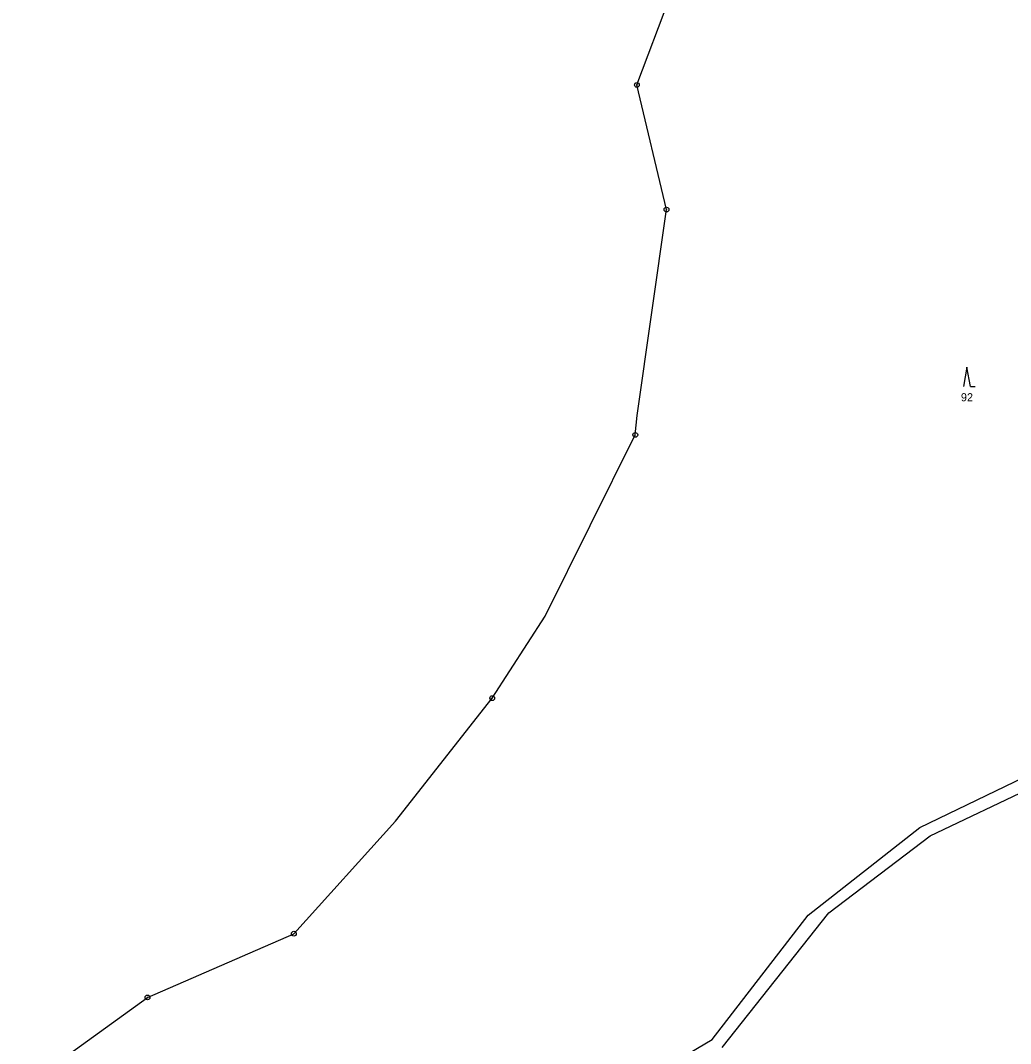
# Model space of a CAD drawing. Extents: x -601877 to -599786, y -1122905 to -1121218.
# Drawn here: x -601358.8 to -601151.3, y -1121749.5 to -1121535.2 of the extents above; entities that cross this region are included whole.
import ezdxf
from ezdxf.enums import TextEntityAlignment as Align

# ---------------------------------------------------------------- set-up
doc = ezdxf.new("R2010")
doc.units = 0
doc.header["$LTSCALE"] = 0.68
for name, color, linetype, lineweight in [('1', 7, 'Continuous', 25), ('3', 7, 'Continuous', 25), ('8', 7, 'Continuous', 25)]:
    doc.layers.add(name, color=color, linetype=linetype, lineweight=lineweight)
doc.layers.add('2', color=7, linetype='Continuous')

msp = doc.modelspace()

# ---------------------------------------------------------------- linework, layer by layer
at = {"layer": '1'}
for p, q in [((-601229.61, -1121548.67), (-601218.56, -1121519.2)), ((-601223.41, -1121574.79), (-601229.61, -1121548.67)), ((-601229.57, -1121617.92), (-601223.41, -1121574.79)), ((-601229.95, -1121622), (-601229.57, -1121617.92)), ((-601248.82, -1121660.01), (-601229.95, -1121622)), ((-601259.92, -1121677.17), (-601248.82, -1121660.01)), ((-601280.22, -1121702.97), (-601259.92, -1121677.17)), ((-601170.32, -1121704.29), (-601111.3, -1121675.76)), ((-601168.15, -1121706.02), (-601108.49, -1121677.47)), ((-601301.49, -1121726.53), (-601280.22, -1121702.97)), ((-601193.74, -1121722.61), (-601170.32, -1121704.29)), ((-601189.37, -1121722.16), (-601168.15, -1121706.02)), ((-601211.78, -1121750.4), (-601189.37, -1121722.16)), ((-601213.82, -1121748.69), (-601193.74, -1121722.61)), ((-601332.16, -1121739.88), (-601301.49, -1121726.53)), ((-601358.77, -1121759.06), (-601332.16, -1121739.88)), ((-601220.34, -1121752.57), (-601213.82, -1121748.69))]:
    msp.add_line(p, q, dxfattribs=at)
at = {"layer": '3'}
msp.add_line((-601159.71, -1121611.84), (-601158.714, -1121611.84), dxfattribs=at)
msp.add_lwpolyline([(-601159.71, -1121611.84), (-601160.46, -1121607.84), (-601161.21, -1121611.84)], dxfattribs=at)
at = {"layer": '8'}
for centre, radius in [((-601229.61, -1121548.6699), 0.5), ((-601229.61, -1121548.6699), 0.0303), ((-601223.41, -1121574.7899), 0.5), ((-601223.41, -1121574.7899), 0.0303), ((-601229.95, -1121621.9999), 0.5), ((-601229.95, -1121621.9999), 0.0303), ((-601259.92, -1121677.1699), 0.5), ((-601259.92, -1121677.1699), 0.0303), ((-601301.49, -1121726.5299), 0.5), ((-601301.49, -1121726.5299), 0.0303), ((-601332.16, -1121739.8799), 0.5), ((-601332.16, -1121739.8799), 0.0303)]:
    msp.add_circle(centre, radius, dxfattribs=at)

# ---------------------------------------------------------------- texts
at = {"layer": '2'}
msp.add_text('92', height=1.7, dxfattribs=at).set_placement((-601160.459, -1121614.965), align=Align.CENTER)

doc.saveas('drawing.dxf')
